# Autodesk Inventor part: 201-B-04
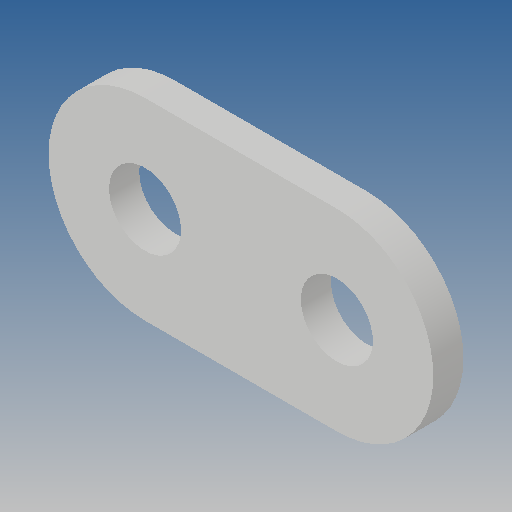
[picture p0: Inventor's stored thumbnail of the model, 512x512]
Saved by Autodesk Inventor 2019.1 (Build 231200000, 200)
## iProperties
Created: 2012-01
Part Number: 201-B-04
Material: Ogólny
Document SubType Name: Modeling
Designer: CADENGINEERING4
Density: 1 g/cm^3
Appearance: Domyślna
Author: CADENGINEERING4
Revision Number: ÈÎºÎ
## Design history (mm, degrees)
feature "À­Éì1"
node "Bryła1"
